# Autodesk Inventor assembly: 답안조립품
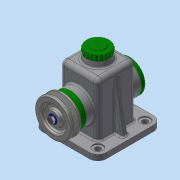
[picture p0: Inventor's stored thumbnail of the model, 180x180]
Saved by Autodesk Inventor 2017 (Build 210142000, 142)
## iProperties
Part Number: 답안조립품
Material: 일반
Document SubType Name: Assembly
Designer: MRC
Author: MRC
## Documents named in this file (14)
- C:\Users\MRC\Desktop\700907V1010\답안조립품.iam
- C:\Users\MRC\Desktop\700907V1010\본체.ipt
- C:\Users\MRC\Desktop\700907V1010\축.ipt
- C:\Users\MRC\Desktop\700907V1010\V-벨트풀리.ipt
- C:\Users\MRC\Desktop\700907V1010\키 5 x 5 x 14.ipt
- C:\Users\MRC\Desktop\700907V1010\베어링 15 x 35 x 11.ipt
- C:\Users\MRC\Desktop\700907V1010\멈춤링 15 x 1.ipt
- C:\Users\MRC\Desktop\700907V1010\앞커버.ipt
- C:\Users\MRC\Desktop\700907V1010\볼트 M4 x 10.ipt
- C:\Users\MRC\Desktop\700907V1010\볼트 M6 x 12.ipt
- C:\Users\MRC\Desktop\700907V1010\뒤커버.ipt
- C:\Users\MRC\Desktop\700907V1010\상부캡.ipt
- C:\Users\MRC\Desktop\700907V1010\와셔.ipt
- C:\Users\MRC\Desktop\700907V1010\오일실 15 25 7.ipt
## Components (1 placed, 1 different names)
1. V-벨트풀리:1
